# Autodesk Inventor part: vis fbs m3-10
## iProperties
Author: chr
Created: 2002-03
Part Number: vis fbs m3-10
Material: Par défaut
Document SubType Name: Modélisation
Designer: chr
Control State: 0
Master: False
Checked Out: False
PropertySet Name: Design Tracking Control
Shininess: 20.0
Angle Display Precision: 2
Document Length Units: 11269
Document Angle Units: 11283
Document Time Units: 11279
Document Mass Units: 11290
Document Length Units Precision: 3
Document Angle Units Precision: 2
Compacted: False
PropertySet Name: _Private Model Information
Density: 0.0
Volumn: 0.0
Area: 0.0
PropertySet Name: Model Information
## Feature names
1. Base1
